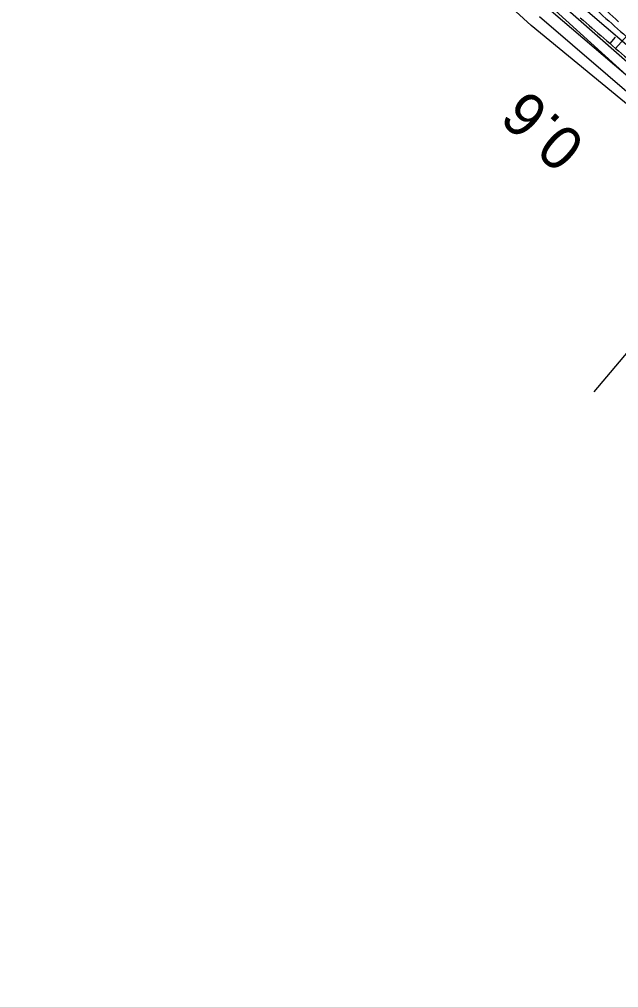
# Model space of a CAD drawing. Extents: x -495905 to -478420, y -1113297 to -1107716.
# Drawn here: x -481388.3 to -481292.1, y -1113161.7 to -1113006.1 of the extents above; entities that cross this region are included whole.
import ezdxf

# ---------------------------------------------------------------- set-up
doc = ezdxf.new("R2010")
doc.units = 0
for name, color, linetype in [('01_OBVOD PÚ', 7, 'Continuous'), ('2D_VRSTEVNICE', 7, 'Continuous'), ('C11_HATCH_SLOPE_R', 7, 'Continuous'), ('C11_HECTOMETRY', 7, 'Continuous'), ('C11_HLBODY', 7, 'Continuous'), ('C11_HRANA_TELESO', 7, 'Continuous'), ('C11_KORUNA', 7, 'Continuous'), ('C11_OSA', 7, 'Continuous'), ('C11_PRIKOP', 7, 'Continuous'), ('ODVODNĚNÍ PLOŠNÉ', 7, 'Continuous'), ('zamereni', 7, 'Continuous')]:
    doc.layers.add(name, color=color, linetype=linetype)

msp = doc.modelspace()

# ---------------------------------------------------------------- linework, layer by layer
at = {"layer": '01_OBVOD PÚ'}
msp.add_line((-481378.69, -1112935.08), (-481286.24, -1113019.27), dxfattribs=at)
at = {"layer": '2D_VRSTEVNICE'}
msp.add_open_spline([(-481551.3, -1112756.92), (-481547.44, -1112761.88), (-481547.11, -1112762.46), (-481545.92, -1112763.5), (-481537.58, -1112762.56), (-481513.68, -1112779.11), (-481513.68, -1112779.11), (-481513.68, -1112779.11), (-481491.05, -1112801.05), (-481482.63, -1112813.08), (-481477.05, -1112818.52), (-481476.8, -1112818.75), (-481456.22, -1112823.29), (-481442.02, -1112835.86), (-481424.8, -1112850.42), (-481413.21, -1112859.51), (-481391.62, -1112878.03), (-481383.26, -1112885.76), (-481360.32, -1112899.5), (-481357.85, -1112904.16), (-481349.13, -1112925.41), (-481341.11, -1112928.52), (-481329.78, -1112937.87), (-481311.64, -1112957.65), (-481301.83, -1112966.08), (-481283.86, -1112978.01), (-481278.86, -1112980.3), (-481258.37, -1112999.07), (-481255.38, -1113002.96), (-481236.21, -1113021.08), (-481230.44, -1113026.21), (-481206.76, -1113043.85), (-481197.57, -1113052.01), (-481170.89, -1113066.19)], degree=2, dxfattribs=at)
at = {"layer": 'C11_HATCH_SLOPE_R'}
for p, q in [((-481290.22, -1113008.14), (-481292.57, -1113010.77)), ((-481292.66, -1113008.98), (-481293.52, -1113009.95))]:
    msp.add_line(p, q, dxfattribs=at)
at = {"layer": 'C11_HLBODY'}
msp.add_line((-481276.9, -1113043.24), (-481296.08, -1113065.92), dxfattribs=at)
at = {"layer": 'C11_HRANA_TELESO'}
for centre, radius, start, end in [((-480504.17, -1112098.34), 1205.86, 228.81268, 229.05144), ((-480504, -1112098.59), 1205.78, 229.0375, 229.27626)]:
    msp.add_arc(centre, radius, start, end, dxfattribs=at)
at = {"layer": 'C11_KORUNA'}
msp.add_arc((-480489, -1112111.78), 1202.25, 227.84959, 228.08832, dxfattribs=at)
at = {"layer": 'C11_OSA'}
msp.add_arc((-480489, -1112111.78), 1200, 227.63347, 229.77292, dxfattribs=at)
at = {"layer": 'C11_PRIKOP'}
for centre, radius, start, end in [((-480490.05, -1112110.84), 1203.22, 227.91673, 228.15546), ((-480490.35, -1112110.58), 1203.21, 228.17447, 228.4132)]:
    msp.add_arc(centre, radius, start, end, dxfattribs=at)
at = {"layer": 'ODVODNĚNÍ PLOŠNÉ'}
msp.add_lwpolyline([(-481426.16, -1112884.94), (-481383.76, -1112925.83), (-481349.63, -1112963.6), (-481309.8, -1112998.79), (-481273.87, -1113029.5), (-481233.31, -1113065.48), (-481187.99, -1113103.18), (-481112.71, -1113161.68), (-481093.99, -1113137.73), (-481062.38, -1113109.2), (-481034.56, -1113086.63), (-481009.15, -1113073.9), (-480966.25, -1113062.37), (-481002.17, -1113037.77), (-481044.22, -1113007.58), (-481079.03, -1112980.74), (-481118.73, -1112955.48), (-481144.71, -1112930.52), (-481180.63, -1112905.92), (-481223.18, -1112868.84)], dxfattribs=at)
at = {"layer": 'zamereni'}
for p, q in [((-481335.55, -1112979.92), (-481306.11, -1113007.1)), ((-481301.22, -1113001.2), (-481283.74, -1113016.26)), ((-481285.11, -1113017.91), (-481302.42, -1113002.63)), ((-481304.78, -1113005.64), (-481287.37, -1113020.65)), ((-481288.74, -1113021.37), (-481306.11, -1113007.1))]:
    msp.add_line(p, q, dxfattribs=at)

# ---------------------------------------------------------------- texts
at = {"layer": 'C11_HECTOMETRY'}
msp.add_text('0.6', height=6.999, rotation=138.0427, dxfattribs=at).set_placement((-481297.1, -1113025.83))

doc.saveas('drawing.dxf')
